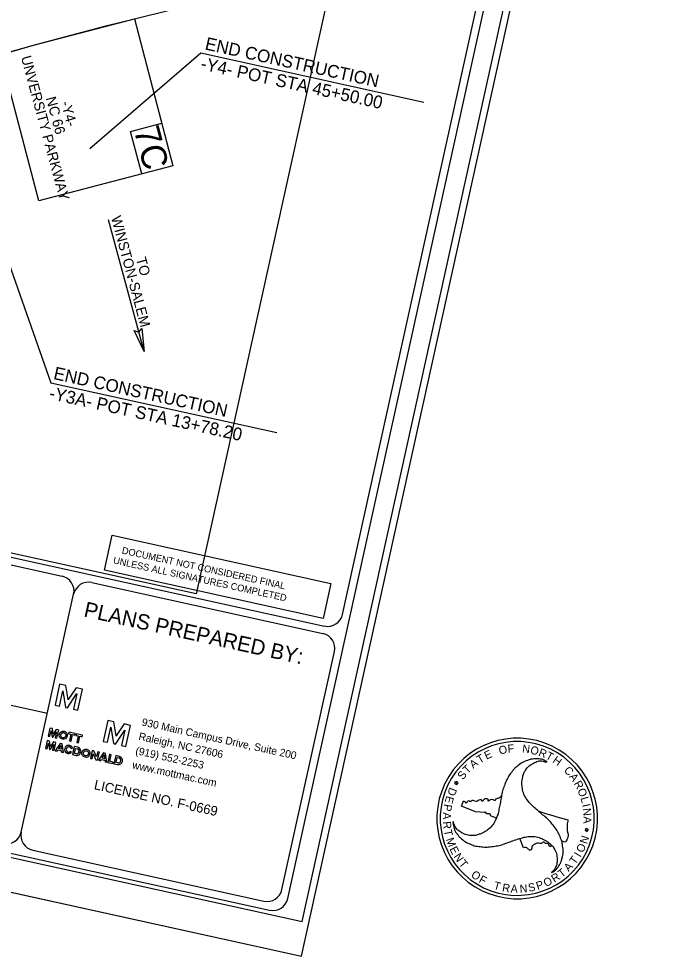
# Model space of a CAD drawing. Extents: x 1609449 to 1623942, y 894240 to 902860.
# Drawn here: x 1621409 to 1623942, y 894240 to 897935 of the extents above; entities that cross this region are included whole.
import ezdxf

# ---------------------------------------------------------------- set-up
doc = ezdxf.new("R2010")
doc.units = 0
for name, color, linetype in [('Old_Level_1', 7, 'Continuous'), ('Old_Level_2', 7, 'Continuous'), ('Old_Level_40', 7, 'Continuous'), ('Prop DSN Text', 7, 'Continuous'), ('Prop Horizontal Alignment Station Label', 7, 'Continuous'), ('Prop Terminator CELL', 7, 'Continuous'), ('Scratch_Level_0', 7, 'Continuous'), ('Scratch_Level_1', 7, 'Continuous'), ('Sheet Cutting Line CELL', 7, 'Continuous'), ('Sheet Plot Border Inside CELL', 7, 'Continuous'), ('Sheet Plot Border Outside CELL', 7, 'Continuous'), ('Sheet Sticker Exception Certification CELL', 7, 'Continuous'), ('Sheet Title CELL', 7, 'Continuous')]:
    doc.layers.add(name, color=color, linetype=linetype)

msp = doc.modelspace()

# ---------------------------------------------------------------- linework, layer by layer
at = {"layer": 'Old_Level_1'}
for p, q in [((1621848.4, 897490.9), (1621971.4, 897523.5)), ((1621893, 897323), (1621848.4, 897490.9))]:
    msp.add_line(p, q, dxfattribs=at)
for points in [[(1620396.2, 898448.3), (1620661.8, 898448.3), (1620661.8, 897662.4), (1621336.9, 897793.5), (1621466.5, 897830.2), (1621864, 897934.4), (1622007.2, 897969.4), (1621831.8, 898938.5), (1620355.8, 898671.4)], [(1621336.9, 897793.5), (1621372.5, 897803.4), (1621466.5, 897830.2), (1621756.4, 897907.9), (1621864, 897934.4), (1622015.4, 897355), (1621487.4, 897217.1)]]:
    msp.add_lwpolyline(points, close=True, dxfattribs=at)
at = {"layer": 'Old_Level_2'}
for p, q in [((1621569.6, 895312.9), (1621551.4, 895230.1)), ((1621594.2, 895307.5), (1621569.6, 895312.9)), ((1621602.9, 895251.9), (1621594.2, 895307.5)), ((1621568.8, 895226.2), (1621582, 895285.8)), ((1621582, 895285.8), (1621582.2, 895285.7)), ((1621582.2, 895285.7), (1621592.4, 895221.1)), ((1621600, 895219.4), (1621636.4, 895274)), ((1621634.7, 895298.6), (1621603.4, 895251.8)), ((1621636.7, 895273.9), (1621623.5, 895214.2)), ((1621659.2, 895293.1), (1621634.7, 895298.6)), ((1621636.4, 895274), (1621636.7, 895273.9)), ((1621641, 895210.3), (1621659.2, 895293.1)), ((1621551.4, 895230.1), (1621568.8, 895226.2)), ((1621602.7, 895251.2), (1621602.9, 895251.9)), ((1621603.2, 895251.1), (1621602.7, 895251.2)), ((1621603.4, 895251.8), (1621603.2, 895251.1)), ((1621592.4, 895221.1), (1621600, 895219.4)), ((1621623.5, 895214.2), (1621641, 895210.3)), ((1621758.9, 895170), (1621740.7, 895087.2)), ((1621783.5, 895164.6), (1621758.9, 895170)), ((1621792.2, 895109.1), (1621783.5, 895164.6)), ((1621824, 895155.7), (1621792.7, 895109)), ((1621848.5, 895150.3), (1621824, 895155.7)), ((1621531.4, 895139.4), (1621524.4, 895107.8)), ((1621531, 895106.3), (1621536, 895129.1)), ((1621540.8, 895137.4), (1621531.4, 895139.4)), ((1621536, 895129.1), (1621536.3, 895129.1)), ((1621536, 895129.1), (1621536.3, 895129.1)), ((1621536.3, 895129.1), (1621540.1, 895104.3)), ((1621544.3, 895115.9), (1621540.8, 895137.4)), ((1621543.2, 895103.7), (1621557.1, 895124.5)), ((1621556.5, 895133.9), (1621544.3, 895115.9)), ((1621557.3, 895124.5), (1621552.3, 895101.7)), ((1621565.8, 895131.9), (1621556.5, 895133.9)), ((1621557.1, 895124.5), (1621557.3, 895124.5)), ((1621557.1, 895124.5), (1621557.3, 895124.5)), ((1621557.1, 895124.5), (1621557.3, 895124.5)), ((1621558.9, 895100.2), (1621565.8, 895131.9)), ((1621558.9, 895100.2), (1621565.8, 895131.9)), ((1621758.1, 895083.4), (1621771.2, 895142.9)), ((1621771.2, 895142.9), (1621771.5, 895142.8)), ((1621771.5, 895142.8), (1621781.7, 895078.2)), ((1621789.3, 895076.5), (1621825.7, 895131.2)), ((1621826, 895131.1), (1621812.8, 895071.3)), ((1621825.7, 895131.2), (1621826, 895131.1)), ((1621830.3, 895067.5), (1621848.5, 895150.3)), ((1621520.6, 895090.3), (1621513.6, 895058.7)), ((1621529.9, 895088.3), (1621520.6, 895090.3)), ((1621524.4, 895107.8), (1621531, 895106.3)), ((1621533.4, 895066.8), (1621529.9, 895088.3)), ((1621545.6, 895084.8), (1621533.4, 895066.8)), ((1621540.1, 895104.3), (1621543.2, 895103.7)), ((1621555, 895082.7), (1621545.6, 895084.8)), ((1621548, 895051.1), (1621555, 895082.7)), ((1621552.3, 895101.7), (1621558.9, 895100.2)), ((1621740.7, 895087.2), (1621758.1, 895083.4)), ((1621792, 895108.3), (1621792.2, 895109.1)), ((1621792.5, 895108.2), (1621792, 895108.3)), ((1621792.7, 895109), (1621792.5, 895108.2)), ((1621513.6, 895058.7), (1621520.2, 895057.2)), ((1621520.2, 895057.2), (1621525.2, 895080)), ((1621525.2, 895080), (1621525.5, 895080)), ((1621525.5, 895080), (1621529.3, 895055.2)), ((1621529.3, 895055.2), (1621532.3, 895054.6)), ((1621532.3, 895054.6), (1621546.2, 895075.4)), ((1621546.5, 895075.3), (1621541.5, 895052.5)), ((1621541.5, 895052.5), (1621548, 895051.1)), ((1621546.2, 895075.4), (1621546.5, 895075.3)), ((1621616, 895042.9), (1621611.1, 895046.8)), ((1621616, 895043), (1621611.1, 895046.8)), ((1621614.5, 895058.8), (1621620.6, 895060.1)), ((1621614.5, 895058.8), (1621620.6, 895060.1)), ((1621623, 895050.5), (1621619.7, 895035.3)), ((1621626.7, 895067), (1621623, 895050.5)), ((1621641.1, 895063.7), (1621626.7, 895067)), ((1621627.6, 895039.9), (1621632, 895059.7)), ((1621632, 895059.7), (1621639.8, 895057.9)), ((1621781.7, 895078.2), (1621789.3, 895076.5)), ((1621812.8, 895071.3), (1621830.3, 895067.5)), ((1621619.7, 895035.3), (1621634.1, 895032.1)), ((1621635.5, 895038.2), (1621627.6, 895039.9)), ((1621786.9, 895014.4), (1621783.5, 894999.2)), ((1621790.5, 895030.9), (1621786.9, 895014.4)), ((1621790.5, 895030.9), (1621790.5, 895030.9)), ((1621804.9, 895027.7), (1621790.5, 895030.9)), ((1621791.4, 895003.8), (1621795.8, 895023.6)), ((1621795.8, 895023.6), (1621803.6, 895021.8)), ((1621803.6, 895021.6), (1621803.6, 895021.6)), ((1621783.5, 894999.2), (1621798, 894996)), ((1621799.3, 895002.1), (1621791.4, 895003.8))]:
    msp.add_line(p, q, dxfattribs=at)
for points in [[(1621604.3, 895117.3), (1621613.4, 895115.3), (1621607.7, 895089.4), (1621614.6, 895087.9), (1621620.3, 895113.8), (1621629.4, 895111.8), (1621630.7, 895117.6), (1621605.6, 895123.1), (1621604.3, 895117.3)], [(1621633.4, 895110.9), (1621642.5, 895108.9), (1621636.8, 895083), (1621643.7, 895081.5), (1621649.4, 895107.3), (1621658.5, 895105.3), (1621659.8, 895111.2), (1621634.7, 895116.7), (1621633.4, 895110.9)], [(1621551.8, 895050.3), (1621559.4, 895048.6), (1621562.6, 895053.5), (1621576.3, 895050.4), (1621577.2, 895044.7), (1621584.5, 895043.1), (1621579.3, 895077.4), (1621571, 895079.2), (1621551.8, 895050.3)], [(1621565.7, 895058.9), (1621573.8, 895071.4), (1621575.8, 895056.6), (1621565.7, 895058.9)], [(1621701.7, 895038.7), (1621701.9, 895038.7), (1621712.6, 895014.8), (1621719, 895013.4), (1621725.9, 895045.1), (1621719.3, 895046.5), (1621714.9, 895026.5), (1621704.4, 895049.8), (1621697.8, 895051.3), (1621690.8, 895019.6), (1621697.2, 895018.2), (1621701.7, 895038.7)], [(1621723, 895012.5), (1621730.6, 895010.9), (1621733.8, 895015.7), (1621747.5, 895012.7), (1621748.3, 895007), (1621755.7, 895005.4), (1621750.5, 895039.7), (1621742.1, 895041.5), (1621723, 895012.5)], [(1621736.8, 895021.2), (1621744.9, 895033.7), (1621747, 895018.9), (1621736.8, 895021.2)], [(1621779.7, 895000), (1621780.9, 895005.6), (1621767.3, 895008.6), (1621773, 895034.7), (1621766.4, 895036.2), (1621759.5, 895004.5), (1621779.7, 895000)], [(1621779.7, 895000), (1621780.9, 895005.6), (1621767.3, 895008.6), (1621773, 895034.7), (1621766.4, 895036.2), (1621759.5, 895004.5), (1621779.7, 895000.1), (1621780.9, 895005.6)]]:
    msp.add_lwpolyline(points, dxfattribs=at)
msp.add_arc((1621801.4, 895011.9), 16.2, 257.5755, 77.5755, dxfattribs=at)
for centre, major_axis, ratio in [((1621583.9, 895111.3), (3.5, 15.8), 0.993118), ((1621583.9, 895111.3), (2.3, 10.3), 0.916103), ((1621673.1, 895040.1), (3.5, 15.8), 0.993118), ((1621673.1, 895040.1), (2.3, 10.3), 0.916103)]:
    msp.add_ellipse(centre, major_axis=major_axis, ratio=ratio, dxfattribs=at)
for centre, major_axis, ratio, start_param, end_param in [((1621605.3, 895055.1), (3.5, 15.8), 0.993118, 5.246647, 10.366427), ((1621605.3, 895055.1), (3.5, 15.8), 0.993118, 5.246647, 10.366427), ((1621605.3, 895055.1), (2.3, 10.3), 0.916103, 5.276876, 10.296021), ((1621605.3, 895055.1), (2.3, 10.3), 0.916103, 5.276876, 9.424778), ((1621605.3, 895055.1), (2.3, 10.3), 0.916103, 3.141593, 4.012835), ((1621637.6, 895047.9), (-3.5, -15.8), 0.930276, 0, 3.141593), ((1621637.6, 895048.1), (-2.18, -9.87), 0.900832, 0, 3.141593), ((1621801.5, 895012), (-2.18, -9.87), 0.900832, 0, 3.141593)]:
    msp.add_ellipse(centre, major_axis=major_axis, ratio=ratio, start_param=start_param, end_param=end_param, dxfattribs=at)
at = {"layer": 'Prop DSN Text'}
msp.add_line((1621901.8, 896622.9), (1621761.5, 897142.6), dxfattribs=at)
at = {"layer": 'Prop Horizontal Alignment Station Label'}
for p, q in [((1621688.3, 897423.7), (1622125.3, 897800)), ((1622125.3, 897800), (1623003.7, 897606.4)), ((1621087, 897764.3), (1621535, 896499.9)), ((1621535, 896499.9), (1622425.3, 896303.7))]:
    msp.add_line(p, q, dxfattribs=at)
at = {"layer": 'Prop Terminator CELL'}
msp.add_lwpolyline([(1621893.3, 896713.9), (1621901.8, 896622.9), (1621862.7, 896706.2), (1621881.2, 896699.2)], close=True, dxfattribs=at)
at = {"layer": 'Scratch_Level_0'}
msp.add_lwpolyline([(1615937.3, 900755.3), (1622890.3, 899223.5), (1622107.1, 895668.6), (1615154.1, 897200.4)], close=True, dxfattribs=at)
at = {"layer": 'Scratch_Level_1'}
msp.add_lwpolyline([(1615937.3, 900755.3), (1622890.3, 899223.5), (1622107.1, 895668.6), (1615154.1, 897200.4)], close=True, dxfattribs=at)
at = {"layer": 'Sheet Cutting Line CELL'}
msp.add_line((1612654.8, 896414.4), (1622522.2, 894240.5), dxfattribs=at)
at = {"layer": 'Sheet Plot Border Inside CELL'}
msp.add_lwpolyline([(1612759.9, 896529.1), (1622524.8, 894377.7), (1623886.8, 900560.1), (1614122, 902711.4)], close=True, dxfattribs=at)
at = {"layer": 'Sheet Plot Border Outside CELL'}
msp.add_lwpolyline([(1623942.2, 900685.8), (1614074.8, 902859.7), (1612654.8, 896414.4), (1622522.2, 894240.5)], close=True, dxfattribs=at)
at = {"layer": 'Sheet Sticker Exception Certification CELL'}
for p, q in [((1621745.7, 895761.5), (1621776, 895899.2)), ((1621776, 895899.2), (1622637.4, 895709.4)), ((1622607, 895571.7), (1621745.7, 895761.5)), ((1622637.4, 895709.4), (1622607, 895571.7))]:
    msp.add_line(p, q, dxfattribs=at)
at = {"layer": 'Sheet Title CELL'}
for p, q in [((1614291.7, 897374.7), (1622612.2, 895541.6)), ((1620408.5, 895996.4), (1621579, 895738.5)), ((1621696.2, 895712.6), (1622605.8, 895512.3)), ((1621418.1, 894729.4), (1621624.7, 895667)), ((1620228.4, 895483.2), (1621521.4, 895198.3)), ((1623488.3, 895007.3), (1623487.5, 895006.9)), ((1623488.3, 895007.3), (1623487.5, 895006.9)), ((1623125.3, 894918.7), (1623128.6, 894923.1)), ((1623130.4, 894920.4), (1623125.3, 894918.7)), ((1623128.6, 894923.1), (1623125.6, 894927.7)), ((1623125.6, 894927.7), (1623130.8, 894925.8)), ((1623133.5, 894915.8), (1623130.4, 894920.4)), ((1623130.8, 894925.8), (1623133.9, 894930.1)), ((1623133.7, 894921.3), (1623133.5, 894915.8)), ((1623139.1, 894922.8), (1623133.7, 894921.3)), ((1623133.9, 894930.1), (1623134, 894924.7)), ((1623134, 894924.7), (1623139.1, 894922.8)), ((1623151.5, 894831.6), (1623158.6, 894849.3)), ((1623207.1, 894809), (1623151.5, 894831.6)), ((1623242.9, 894806.7), (1623207.1, 894809)), ((1623289.8, 894785.1), (1623266.4, 894794)), ((1623453.7, 894813.2), (1623453.7, 894813.2)), ((1623641.4, 894738.4), (1623638.2, 894734.1)), ((1623638.2, 894734.1), (1623643.2, 894735.6)), ((1623643.4, 894741.1), (1623638.3, 894743)), ((1623638.3, 894743), (1623641.4, 894738.4)), ((1623643.2, 894735.6), (1623646.3, 894731.1)), ((1623646.7, 894745.3), (1623643.4, 894741.1)), ((1623646.3, 894731.1), (1623646.6, 894736.6)), ((1623646.6, 894736.6), (1623651.9, 894738.2)), ((1623646.8, 894739.9), (1623646.7, 894745.3)), ((1623651.9, 894738.2), (1623646.8, 894739.9)), ((1623396.1, 894668.3), (1623381, 894704.4)), ((1623381, 894704.4), (1623381, 894704.4)), ((1623668.3, 894675.2), (1623668.3, 894675.2))]:
    msp.add_line(p, q, dxfattribs=at)
for points in [[(1622467.7, 894467.5), (1623797.4, 900502.7)], [(1622683.7, 895587.2), (1623761.6, 900479.9)], [(1613724.2, 896332.3), (1622396.2, 894421.7)], [(1622444.9, 894503.2), (1622651.4, 895440.8)], [(1621463.9, 894657.9), (1622373.4, 894457.6)]]:
    msp.add_lwpolyline(points, dxfattribs=at)
for centre, radius, start, end in [((1621566.1, 895679.9), 60, 347.5755, 77.5755), ((1621683.3, 895654.1), 60, 77.5755, 167.5755), ((1622625.2, 895600.4), 60, 257.5755, 347.5755), ((1622592.9, 895453.9), 60, 347.5755, 77.5755), ((1623371.1, 894783.3), 316.3, 339.9966, 159.9966), ((1623371.1, 894783.3), 303.1, 339.9966, 159.9966), ((1623371.1, 894783.3), 316.3, 159.9966, 339.9966), ((1623371.1, 894783.3), 303.1, 159.9966, 339.9966), ((1623993.4, 896391.1), 1667.7, 245.6751, 245.7747), ((1623993.4, 896391.1), 1667.7, 251.1142, 255.3202), ((1621359.6, 894742.7), 60, 257.5755, 347.5755), ((1621476.8, 894716.9), 60, 167.5755, 257.5755), ((1622386.4, 894516.4), 60, 257.5755, 347.5755), ((1622409.2, 894480.7), 60, 257.5755, 347.5755)]:
    msp.add_arc(centre, radius, start, end, dxfattribs=at)
for points in [[(1623487.5, 895006.9), (1623481.5, 895011.1), (1623461.5, 895017.5), (1623439, 895018.3), (1623436.9, 895018), (1623425, 895016.4), (1623411.4, 895012.3), (1623389.7, 895003), (1623370.6, 894988.7), (1623362.7, 894982.5), (1623355.5, 894973.9), (1623341.3, 894955.4), (1623330.5, 894936.3), (1623320.5, 894913.1), (1623313.3, 894892.2), (1623309, 894869.7), (1623304.9, 894847), (1623300.4, 894825.1), (1623295.6, 894802.6), (1623287.9, 894781.3), (1623287.2, 894779.5), (1623275.1, 894758.3), (1623258.7, 894741.8), (1623240.9, 894729.4), (1623231.1, 894724.3), (1623218.4, 894720.2), (1623211.1, 894717.7), (1623195.1, 894715.8), (1623173, 894718.4), (1623153.5, 894726.8), (1623137.5, 894737.7), (1623125.7, 894753.3), (1623118.6, 894772)], [(1623506.7, 894570), (1623513, 894573.1), (1623528.7, 894587.2), (1623540.7, 894606.2), (1623541.7, 894608.1), (1623546, 894619.4), (1623549.4, 894633.3), (1623552.3, 894656.7), (1623549.3, 894680.3), (1623548, 894690.3), (1623544.1, 894700.9), (1623535.2, 894722.5), (1623524.2, 894741.3), (1623508.9, 894761.4), (1623494.3, 894778), (1623477, 894793.3), (1623459.5, 894808.1), (1623442.9, 894822.8), (1623425.6, 894838.5), (1623411.1, 894855.6), (1623410.1, 894857.3), (1623397.4, 894878.5), (1623391.4, 894900.9), (1623389.5, 894922.5), (1623390.2, 894933.3), (1623393, 894946.5), (1623394.3, 894954.2), (1623400.9, 894968.8), (1623414.2, 894986.8), (1623431, 894999.3), (1623448.5, 895007.6), (1623468.1, 895010.1), (1623487.5, 895006.9), (1623488.3, 895007.3)], [(1623158.6, 894849.3), (1623158.6, 894851.2), (1623162.3, 894852), (1623169.4, 894845.5), (1623175, 894847.6), (1623176.1, 894851.3), (1623180.8, 894853.7), (1623186.1, 894850.4), (1623193.7, 894855.2), (1623198.8, 894854.6), (1623208.9, 894850.9), (1623225.1, 894858.6), (1623230.4, 894857.4), (1623230.5, 894853.8), (1623233.4, 894852.1), (1623242.1, 894860.1), (1623243.9, 894861), (1623254.6, 894861.3), (1623256.4, 894858.7), (1623255.5, 894854), (1623256.5, 894852.6), (1623260.4, 894853.7), (1623266.5, 894857.5), (1623275.6, 894858.7), (1623283.9, 894854.4), (1623288, 894861), (1623300.7, 894864.2), (1623304.3, 894867.5), (1623306.4, 894871.6)], [(1623309.1, 894870.3), (1623309, 894869.7), (1623304.9, 894847), (1623300.4, 894825.1), (1623295.6, 894802.6), (1623289.7, 894785.2)], [(1623266.4, 894794), (1623265.7, 894799.1), (1623261.6, 894802.1), (1623254.2, 894801.1), (1623249.6, 894803.1), (1623245.9, 894808.6), (1623242.9, 894806.7)], [(1623546.9, 894694.2), (1623544.1, 894700.9), (1623535.2, 894722.5), (1623524.2, 894741.3), (1623508.9, 894761.4), (1623494.3, 894778), (1623477, 894793.3), (1623459.5, 894808.1), (1623453.7, 894813.2)], [(1623118.6, 894772), (1623118.3, 894764.6), (1623122.7, 894744), (1623133, 894724.1), (1623134.3, 894722.6), (1623141.8, 894712.8), (1623152.1, 894703.3), (1623171.1, 894689), (1623192.9, 894679.8), (1623202.2, 894676), (1623213.7, 894674), (1623236.4, 894671.1), (1623258.1, 894671.1), (1623283.4, 894674.1), (1623304.9, 894678.4), (1623326.8, 894685.9), (1623348.5, 894693.8), (1623369.7, 894700.8), (1623391.7, 894707.6), (1623413.9, 894711.8), (1623416.2, 894711.9), (1623440.6, 894712.2), (1623462.8, 894706.3), (1623482.3, 894697.2), (1623492, 894691.2), (1623501.5, 894682), (1623507.8, 894677.1), (1623517.1, 894664.2), (1623525.8, 894643.8), (1623528.3, 894622.9), (1623526.8, 894603.4), (1623519.2, 894585.3), (1623506.7, 894570)], [(1623570.8, 894777.8), (1623567.8, 894756.5), (1623569.7, 894729.3), (1623571.7, 894714.1), (1623567.6, 894703.2), (1623560.2, 894691), (1623547.1, 894694.3)], [(1623381, 894704.4), (1623391.7, 894707.6), (1623413.9, 894711.8), (1623416.2, 894711.9), (1623440.6, 894712.2), (1623462.8, 894706.3), (1623482.3, 894697.2), (1623492, 894691.2), (1623501.5, 894682), (1623507.3, 894677.3)], [(1623507.1, 894677.3), (1623502.5, 894673.1), (1623497.9, 894674.4), (1623492.3, 894683.5), (1623482, 894685), (1623478.6, 894689.2), (1623475.7, 894690.3), (1623465.5, 894684.1), (1623455.3, 894685.5), (1623435.7, 894679.7), (1623430.1, 894674.3), (1623426.1, 894659.6), (1623421.3, 894658.2), (1623416.9, 894660.5), (1623408.8, 894667.7), (1623396.1, 894668.3)]]:
    msp.add_spline(points, degree=3, dxfattribs=at)

# ---------------------------------------------------------------- texts
at = {"layer": 'Old_Level_1'}
msp.add_text('7C', height=100, rotation=284.886, dxfattribs=at).set_placement((1621860.7, 897496.8))
at = {"layer": 'Old_Level_2'}
for s, p in [('930 Main Campus Drive, Suite 200', (1621890.8, 895149.8)), ('Raleigh, NC 27606', (1621878.4, 895093.5)), ('(919) 552-2253', (1621866, 895037.3)), ('www.mottmac.com', (1621853.6, 894981))]:
    msp.add_text(s, height=30, rotation=347.5755, dxfattribs=at).set_placement(p)
at = {"layer": 'Old_Level_40'}
msp.add_text('PLANS PREPARED BY:', height=60.139, rotation=347.5755, dxfattribs=at).set_placement((1621661.5, 895579.8))
at = {"layer": 'Prop Horizontal Alignment Station Label'}
for s, height, rotation, p in [('END CONSTRUCTION', 50, 347.5755, (1622139, 897813.9)), ('UNVERSITY PARKWAY', 40, 285.127, (1621417.1, 897782.9)), ('-Y4- POT STA 45+50.00', 50, 347.5755, (1622121.8, 897735.7)), ('NC 66', 40, 285.127, (1621514.9, 897621.9)), ('-Y4-', 40, 285.127, (1621574.1, 897604.1)), ('WINSTON-SALEM', 40, 285.0155, (1621771.7, 897151.8)), ('TO', 40, 285.0155, (1621869.6, 896989.4)), ('END CONSTRUCTION', 50, 347.5755, (1621542.5, 896515.2)), ('-Y3A- POT STA 13+78.20', 50, 347.5755, (1621525.3, 896437.1))]:
    msp.add_text(s, height=height, rotation=rotation, dxfattribs=at).set_placement(p)
at = {"layer": 'Sheet Sticker Exception Certification CELL'}
for s, p in [('DOCUMENT NOT CONSIDERED FINAL', (1621812.7, 895827.5)), ('UNLESS ALL SIGNATURES COMPLETED', (1621778.3, 895788.8))]:
    msp.add_text(s, height=27, rotation=347.5755, dxfattribs=at).set_placement(p)
at = {"layer": 'Sheet Title CELL'}
for s, height, rotation, p in [('E', 31.4, 24.1535, (1623249.9, 895014.9)), ('O', 31.6, 12.2142, (1623302, 895035.2)), ('F', 31.6, 5.0673, (1623334.6, 895042.1)), ('N', 31.5, 352.9804, (1623389.5, 895044)), ('O', 31.6, 345.4823, (1623420.1, 895040)), ('R', 31.5, 338.8723, (1623452.4, 895031.6)), ('T', 31.6, 332.2227, (1623480.5, 895020.8)), ('A', 31.6, 38.3244, (1623197.9, 894978.7)), ('T', 31.5, 31.2692, (1623223.5, 894998.9)), ('H', 31.5, 325.138, (1623507.8, 895006.2)), ('S', 31.5, 51.7529, (1623157.3, 894933.6)), ('T', 31.6, 45.3767, (1623175.9, 894957.1)), ('C', 31.4, 312.7956, (1623552.9, 894971.2)), ('LICENSE NO. F-0669', 37.929, 347.5606, (1621702.6, 894899.1)), ('A', 31.5, 305.2986, (1623574.2, 894948)), ('R', 31.5, 298.9347, (1623592.9, 894921.6)), ('D', 31.5, 247.8496, (1623106.2, 894908.3)), ('O', 31.6, 291.8151, (1623607.4, 894895.2)), ('E', 31.4, 254.1375, (1623092.8, 894874.6)), ('L', 31.5, 285.5814, (1623619.9, 894864)), ('P', 31.5, 261.6699, (1623084, 894841.5)), ('I', 31.6, 281.592, (1623626.7, 894837.6)), ('N', 31.5, 275.8919, (1623629.5, 894822.5)), ('A', 31.5, 268.2625, (1623079.2, 894808.1)), ('A', 31.5, 268.46, (1623632.5, 894791.7)), ('R', 31.5, 275.3311, (1623078.5, 894770.8)), ('T', 31.5, 281.9816, (1623082, 894736.2)), ('N', 31.5, 72.2047, (1623645.8, 894680.6)), ('M', 31.5, 289.2167, (1623090, 894701.3)), ('E', 31.5, 296.6834, (1623103.8, 894663.6)), ('O', 31.4, 64.9567, (1623630, 894645.9)), ('N', 31.6, 303.655, (1623119.4, 894633.4)), ('T', 31.5, 54.1712, (1623599.3, 894599.3)), ('I', 31.6, 59.8211, (1623620, 894628.3)), ('T', 31.5, 310.497, (1623139.4, 894603.9)), ('A', 31.6, 47.0868, (1623574.2, 894571.7)), ('O', 31.5, 323.8007, (1623186.5, 894555.8)), ('R', 31.6, 32.8999, (1623517.7, 894529.4)), ('T', 31.4, 38.9997, (1623546.7, 894548.7)), ('F', 31.5, 330.9659, (1623217.5, 894533.7)), ('T', 31.4, 343.8751, (1623275.8, 894506.1)), ('R', 31.6, 350.8318, (1623310.3, 894496.5)), ('S', 31.4, 11.827, (1623417.5, 894494)), ('P', 31.5, 19.0188, (1623451.6, 894501.4)), ('O', 31.6, 25.7108, (1623483.4, 894512.6)), ('A', 31.4, 357.5849, (1623344.7, 894491.5)), ('N', 31.4, 4.6165, (1623382, 894490.5))]:
    msp.add_text(s, height=height, rotation=rotation, dxfattribs=at).set_placement(p)

doc.saveas('drawing.dxf')
